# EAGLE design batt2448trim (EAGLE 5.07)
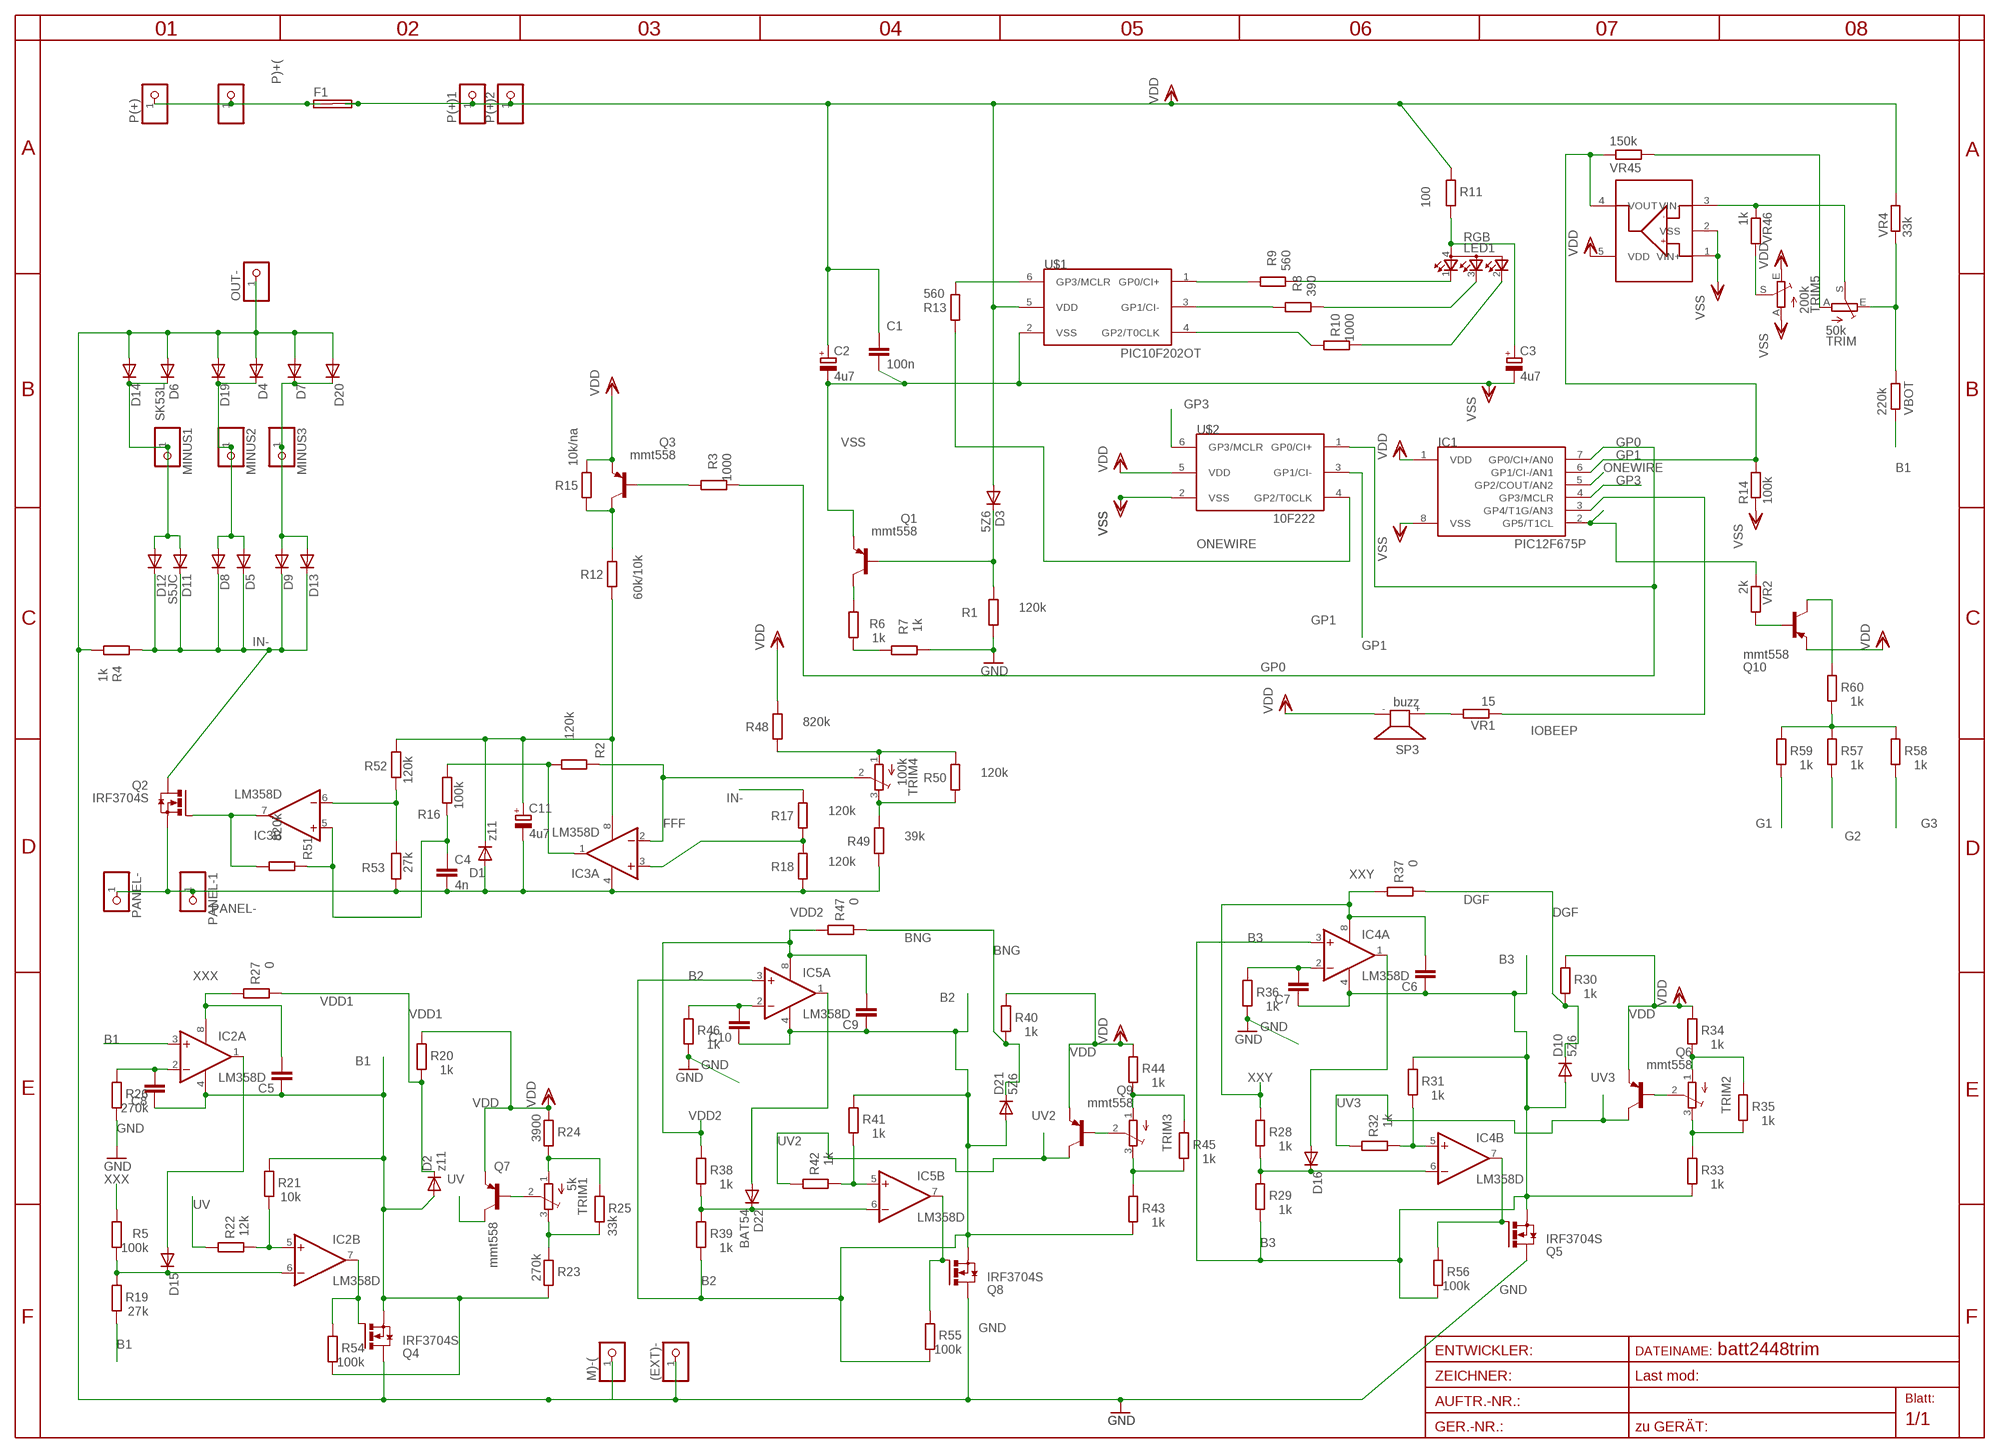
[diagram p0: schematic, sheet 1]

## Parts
(EXT)-  PINHD-1X11MM6  [1X1MM8]
C1  100n  C-EUC1206  [C1206]
C2  4u7  CPOL-EUSMCA  [SMC_A]
C3  4u7  CPOL-EUSMCA  [SMC_A]
C4  4n  C-EUC0805  [C0805]
C5  C-EUC1206  [C1206]
C6  C-EUC1206  [C1206]
C7  C-EUC0805  [C0805]
C8  C-EUC0805  [C0805]
C9  C-EUC1206  [C1206]
C10  C-EUC0805  [C0805]
C11  4u7  CPOL-EUSANYO_SMD_B6  [SANYO-OSCON_SMD_B6]
D1  z11  DIODE-MINIMELF  [MINIMELF]
D2  z11  DIODE-MINIMELF  [MINIMELF]
D3  5Z6  DIODE-MINIMELF  [MINIMELF]
D4  DIODE-SMC  [SMC]
D5  DIODE-SMC  [SMC]
D6  SK53L  DIODE-SMC  [SMC]
D7  DIODE-SMC  [SMC]
D8  DIODE-SMC  [SMC]
D9  DIODE-SMC  [SMC]
D10  5Z6  DIODE-MINIMELF  [MINIMELF]
D11  S5JC  DIODE-SMC  [SMC]
D12  DIODE-SMC  [SMC]
D13  DIODE-SMC  [SMC]
D14  DIODE-SMC  [SMC]
D15  DIODE-MINIMELF  [MINIMELF]
D16  DIODE-MINIMELF  [MINIMELF]
D19  DIODE-SMC  [SMC]
D20  DIODE-SMC  [SMC]
D21  5Z6  DIODE-MINIMELF  [MINIMELF]
D22  BAT54  DIODE-MINIMELF  [MINIMELF]
F1  SHK20L7MM5  [7MM5]
IC1  PIC12F675P  [DIL8]
IC2  LM358D  [SO08]
IC3  LM358D  [SO08]
IC4  LM358D  [SO08]
IC5  LM358D  [SO08]
IC6  MCP6001U  [SOT23-5L]
LED1  RGB  GM1WA55311A  [FULL3528]
M)-(  PINHD-1X11MM6  [1X1MM8]
MINUS1  PINHD-1X12MM3  [1X2MM3]
MINUS2  PINHD-1X12MM3  [1X2MM3]
MINUS3  PINHD-1X12MM3  [1X2MM3]
OUT-  PINHD-1X12MM3  [1X2MM3]
P(+)  PINHD-1X14.5MM  [1X4MM5]
P(+)1  PINHD-1X14.5MM  [1X4MM5]
P(+)2  PINHD-1X13MM2  [1X3MM2]
P)+(  PINHD-1X11X0.4  [1X01]
PANEL-  PINHD-1X12MM3  [1X2MM3]
PANEL-1  PINHD-1X11MM6  [1X1MM8]
Q1  mmt558  BC857ALT1SMD  [SOT23-BEC]
Q2  IRF3704S  [D2PACK]
Q3  mmt558  BC857ALT1SMD  [SOT23-BEC]
Q4  IRF3704S  [D2PACK]
Q5  IRF3704S  [D2PACK]
Q6  mmt558  BC857ALT1SMD  [SOT23-BEC]
Q7  mmt558  BC857ALT1SMD  [SOT23-BEC]
Q8  IRF3704S  [D2PACK]
Q9  mmt558  BC857ALT1SMD  [SOT23-BEC]
Q10  mmt558  BC857ALT1SMD  [SOT23-BEC]
R1  120k  R-EU_R1206  [R1206]
R2  120k  R-EU_R0805  [R0805]
R3  1000  R-EU_R0805  [R0805]
R4  1k  R-EU_0207/25  [0207/25]
R5  100k  R-EU_R1206  [R1206]
R6  1k  R-EU_R1206  [R1206]
R7  1k  R-EU_R1206  [R1206]
R8  390  R-EU_R0805  [R0805]
R9  560  R-EU_R0805  [R0805]
R10  1000  R-EU_R0805  [R0805]
R11  100  R-EU_R1206  [R1206]
R12  60k/10k  R-EU_R1206  [R1206]
R13  560  R-EU_R0805  [R0805]
R14  100k  R-EU_R1206  [R1206]
R15  10k/na  R-EU_R0805  [R0805]
R16  100k  R-EU_R0805  [R0805]
R17  120k  R-EU_R0805  [R0805]
R18  120k  R-EU_R0805  [R0805]
R19  27k  R-EU_R0805  [R0805]
R20  1k  R-EU_R1206  [R1206]
R21  10k  R-EU_R0805  [R0805]
R22  12k  R-EU_R1206  [R1206]
R23  270k  R-EU_R0805  [R0805]
R24  3900  R-EU_R0805  [R0805]
R25  33k  R-EU_R0805  [R0805]
R26  270k  R-EU_R1206  [R1206]
R27  0  R-EU_R1203  [R1203]
R28  1k  R-EU_R1206  [R1206]
R29  1k  R-EU_R0805  [R0805]
R30  1k  R-EU_R1206  [R1206]
R31  1k  R-EU_R0805  [R0805]
R32  1k  R-EU_R1206  [R1206]
R33  1k  R-EU_R0805  [R0805]
R34  1k  R-EU_R0805  [R0805]
R35  1k  R-EU_R0805  [R0805]
R36  1k  R-EU_R1206  [R1206]
R37  0  R-EU_R1203  [R1203]
R38  1k  R-EU_R1206  [R1206]
R39  1k  R-EU_R0805  [R0805]
R40  1k  R-EU_R1206  [R1206]
R41  1k  R-EU_R0805  [R0805]
R42  1k  R-EU_R1206  [R1206]
R43  1k  R-EU_R0805  [R0805]
R44  1k  R-EU_R0805  [R0805]
R45  1k  R-EU_R0805  [R0805]
R46  1k  R-EU_R1206  [R1206]
R47  0  R-EU_R1203  [R1203]
R48  820k  R-EU_R0805  [R0805]
R49  39k  R-EU_R1206  [R1206]
R50  120k  R-EU_R0805  [R0805]
R51  820k  R-EU_R0805  [R0805]
R52  120k  R-EU_R1206  [R1206]
R53  27k  R-EU_R1206  [R1206]
R54  100k  R-EU_R0805  [R0805]
R55  100k  R-EU_R0805  [R0805]
R56  100k  R-EU_R0805  [R0805]
R57  1k  R-EU_0207-17MM5  [0207/17MM5]
R58  1k  R-EU_0207-17MM5  [0207/17MM5]
R59  1k  R-EU_0207/10  [0207/10]
R60  1k  R-EU_R0805  [R0805]
SP3  buzz  KSS12017MM  [KSS1202]
TRIM  50k  TRIM_EU-S64W  [S64W]
TRIM1  5k  TRIM_EU-3223G  [3223G]
TRIM2  TRIM_EU-3223G  [3223G]
TRIM3  TRIM_EU-3223G  [3223G]
TRIM4  100k  TRIM_EU-3223G  [3223G]
TRIM5  200k  TRIM_EU-S64W  [S64W]
U$1  PIC10F202OT  [SOT23-6]
U$2  10F222  PIC10F204OT  [SOT23-6]
VBOT  220k  R-EU_R0805  [R0805]
VR1  15  R-EU_R0805  [R0805]
VR2  2k  R-EU_R0805  [R0805]
VR4  33k  R-EU_R1206  [R1206]
VR45  150k  R-EU_R0805  [R0805]
VR46  1k  R-EU_R0805  [R0805]

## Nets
A: C3.+ LED1.4(A) R11.1
B: LED1.3(CBLUE) R8.1
B1: C5.1 C8.1 D2.A D6.C D11.A D12.A D14.C IC2.3(A:+IN) IC2.4(P:V-) MINUS1.1 Q4.3(S) R19.1 R21.2 R23.1 R54.1 VBOT.1
B2: C9.1 C10.1 D7.C D9.A D13.A D20.C D21.A IC5.3(A:+IN) IC5.4(P:V-) MINUS3.1 Q8.3(S) R39.1 R41.2 R43.1 R55.1
B3: C6.1 C7.1 D4.C D5.A D8.A D10.A D19.C IC4.3(A:+IN) IC4.4(P:V-) MINUS2.1 Q5.3(S) R29.1 R31.2 R33.1 R56.1
BNG: D21.C R40.1 R47.1
BUZZ+: SP3.+ VR1.2
DGF: D10.C R30.1 R37.1
DIGOUT: R57.2 R58.2 R59.2 R60.1
FFF: IC3.2(A:-IN) R2.2 TRIM4.2(S)
G: LED1.2(CGREEN) R10.1
G1: IC2.7(B:OUT) Q4.1(G) R54.2 R59.1
G2: IC5.7(B:OUT) Q8.1(G) R55.2 R57.1
G3: IC4.7(B:OUT) Q5.1(G) R56.2 R58.1
GND: (EXT)-.1 D4.A D6.A D7.A D14.A D19.A D20.A M)-(.1 OUT-.1 Q4.2(D) Q5.2(D) Q8.2(D) R1.2 R4.1 R7.1 R26.1 R36.1 R46.1
GP0: IC1.7(GP0/CI+/AN0) R3.1 U$2.1(GP0/CI+)
GP0C: R9.2 U$1.1(GP0/CI+)
GP1: IC1.6(GP1/CI-/AN1) IC6.4(VOUT) R14.2 U$2.3(GP1/CI-) VR45.1
GP1C: R8.2 U$1.3(GP1/CI-)
GP2C: R10.2 U$1.4(GP2/T0CLK)
GP3: IC1.4(GP3/MCLR) U$2.6(GP3/MCLR)
GP3_2: R13.1 U$1.6(GP3/MCLR)
IN+: F1.1A F1.1B P(+).1 P)+(.1
IN-: D5.C D8.C D9.C D11.C D12.C D13.C Q2.2(D) R4.2 R17.1
IOBEEP: IC1.3(GP4/T1G/AN3) VR1.1
N$1: D15.C IC2.6(B:-IN) R5.1 R19.2
N$2: D3.C Q1.B R1.1
N$4: C11.+ D1.C IC3.8(P:V+) R12.2 R52.1
N$5: TRIM.E VBOT.2 VR4.1
N$6: Q1.C R6.2
N$7: TRIM5.S VR46.2
N$8: Q3.B R3.2
N$9: Q10.B VR2.2
N$10: IC2.5(B:+IN) R21.1 R22.1
N$11: Q3.C R12.1 R15.2
N$12: TRIM.A VR45.2
N$13: IC3.1(A:OUT) R2.1 R16.1
N$14: IC6.3(VIN-) TRIM.S VR46.1
N$16: IC3.3(A:+IN)
N$17: D15.A IC2.1(A:OUT)
N$18: R6.1 R7.2
N$19: R17.2 R18.1
N$20: C8.2 IC2.2(A:-IN) R26.2
N$21: Q7.B TRIM1.2(S)
N$22: R24.1 R25.2 TRIM1.1(A)
N$23: R23.2 R25.1 TRIM1.3(E)
N$24: IC3.6(B:-IN) R52.2 R53.1
N$25: D16.C IC4.6(B:-IN) R28.1 R29.2
N$26: IC4.5(B:+IN) R31.1 R32.1
N$27: Q6.B TRIM2.2(S)
N$30: R34.1 R35.2 TRIM2.1(A)
N$31: R33.2 R35.1 TRIM2.3(E)
N$32: D16.A IC4.1(A:OUT)
N$33: C7.2 IC4.2(A:-IN) R36.2
N$34: Q10.C R60.2
N$35: D22.C IC5.6(B:-IN) R38.1 R39.2
N$36: IC5.5(B:+IN) R41.1 R42.1
N$37: Q9.B TRIM3.2(S)
N$38: IC1.2(GP5/T1CL) VR2.1
N$39: R44.1 R45.2 TRIM3.1(A)
N$40: R43.2 R45.1 TRIM3.3(E)
N$41: D22.A IC5.1(A:OUT)
N$42: C10.2 IC5.2(A:-IN) R46.2
N$43: R49.1 R50.2 TRIM4.3(E)
N$45: R48.2 R50.1 TRIM4.1(A)
N$46: C4.1 IC3.5(B:+IN) R16.2 R51.2
N$47: IC3.7(B:OUT) Q2.1(G) R51.1
ONEWIRE: IC1.5(GP2/COUT/AN2) R13.2 U$2.4(GP2/T0CLK)
PANEL-: C4.2 C11.- D1.A IC3.4(P:V-) PANEL-1.1 PANEL-.1 Q2.3(S) R18.2 R49.2 R53.2
R: LED1.1(CRED) R9.1
UV: Q7.C R22.2
UV2: Q9.C R42.2
UV3: Q6.C R32.2
VDD: C1.1 C2.+ D3.A F1.2A F1.2B IC1.1(VDD) IC6.5(VDD) P(+)1.1 P(+)2.1 Q3.E Q6.E Q7.E Q9.E Q10.E R11.2 R15.1 R20.2 R24.2 R30.2 R34.2 R40.2 R44.2 R48.1 SP3.- TRIM5.E U$1.5(VDD) U$2.5(VDD) VR4.2
VDD1: D2.C R20.1 R27.1
VDD2: C9.2 IC5.8(P:V+) R38.2 R47.2
VSS: C1.2 C2.- C3.- IC1.8(VSS) IC6.1(VIN+) IC6.2(VSS) Q1.E R14.1 TRIM5.A U$1.2(VSS) U$2.2(VSS)
XXX: C5.2 IC2.8(P:V+) R5.2 R27.2
XXY: C6.2 IC4.8(P:V+) R28.2 R37.2

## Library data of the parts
(EXT)- M)-( MINUS1-MINUS3 OUT- P(+) P(+)1 P(+)2 P)+( PANEL- PANEL-1 = pinhead:PINHD-1X1: PIN HEADER
C1 C4-C10 = rcl:C-EU: CAPACITOR, European symbol
C2 C3 C11 = rcl:CPOL-EU: POLARIZED CAPACITOR, European symbol
D1-D16 D19-D22 = diode:DIODE-: DIODE
F1 = fuse:SHK20L: FUSE HOLDER 5 x 20 mm, SH contact, SHH1 Schukat, E1073 Buerklin
IC1 = microchip-3:PIC12F6*: uPC nW 1k Program Flash memory 2x Timer Comparator 10b A/D converter/ 4xIN
IC2-IC5 = linear:LM358: OP AMP also LM158; LM258; LM2904 Source: http://cache.national.com/ds/LM/LM158.pdf
IC6 = microchip-3:MCP6001U
LED1 = led:GM1WA55311A: Chip LED RGB Source: http://document.sharpsma.com/files/GM1WA55311A_SS.pdf
Q1 Q3 Q6 Q7 Q9 Q10 = transistor-pnp:BC857*: PNP Transistror
Q2 Q4 Q5 Q8 = transistor-power:IRF3704: SMPS MOSFET HEXFET® Power MOSFET Source: http://www.irf.com/product-info/datasheets/data/irf3704.pdf
R1-R13 R15-R21 R23-R26 R28-R36 R38-R46 R48-R60 VBOT VR1 VR2 VR4 VR45 VR46 = rcl-2:R-EU_: RESISTOR, European symbol
R14 R22 R27 R37 R47 = rcl:R-EU_: RESISTOR, European symbol
SP3 = buzzer:KSS1201: SPEAKER
TRIM TRIM1-TRIM5 = pot:TRIM_EU-: POTENTIOMETER
U$1 U$2 = microchip-3:PIC10F2*: uPC nW 0,25/0,5k Program Flash memory Comparator

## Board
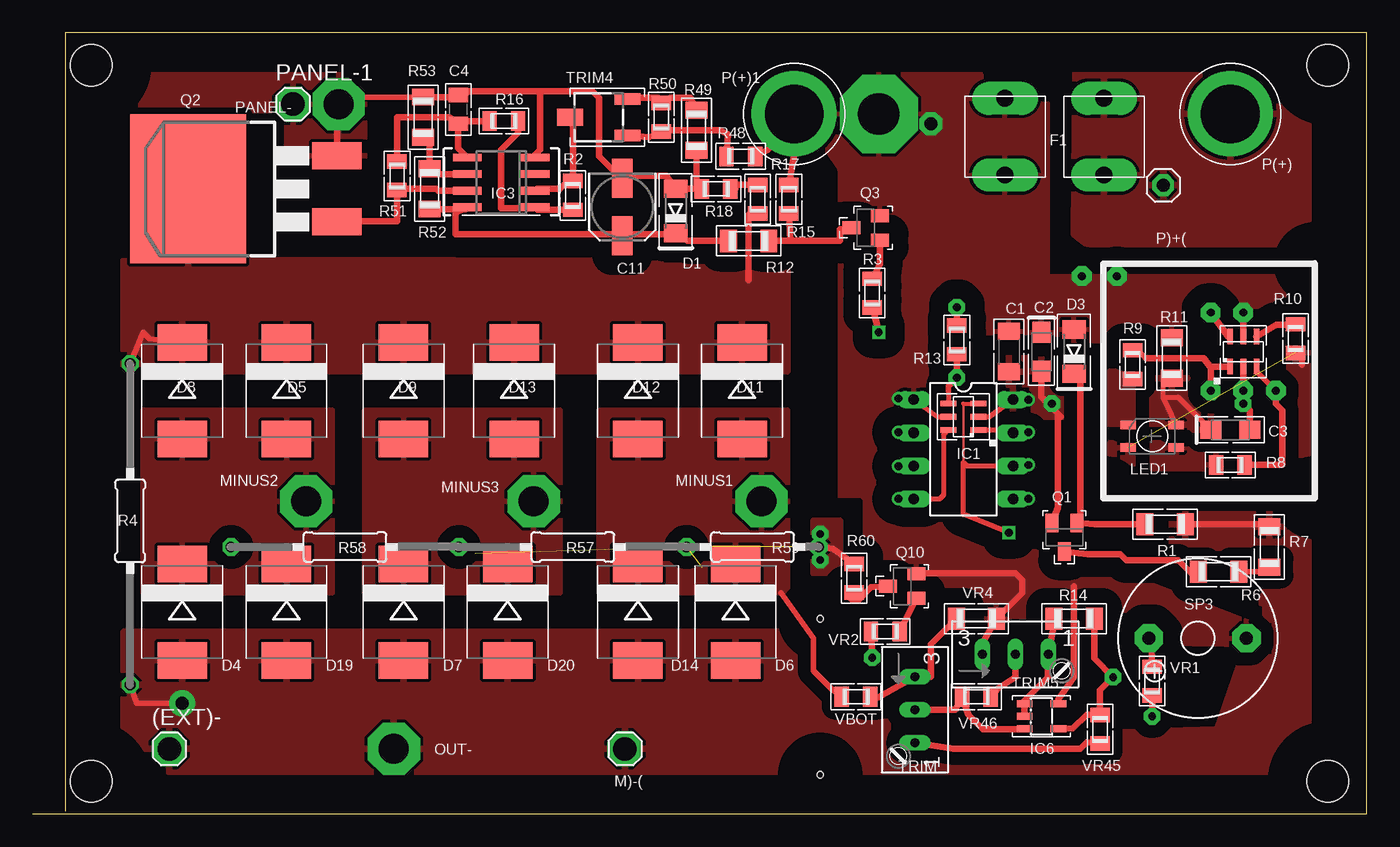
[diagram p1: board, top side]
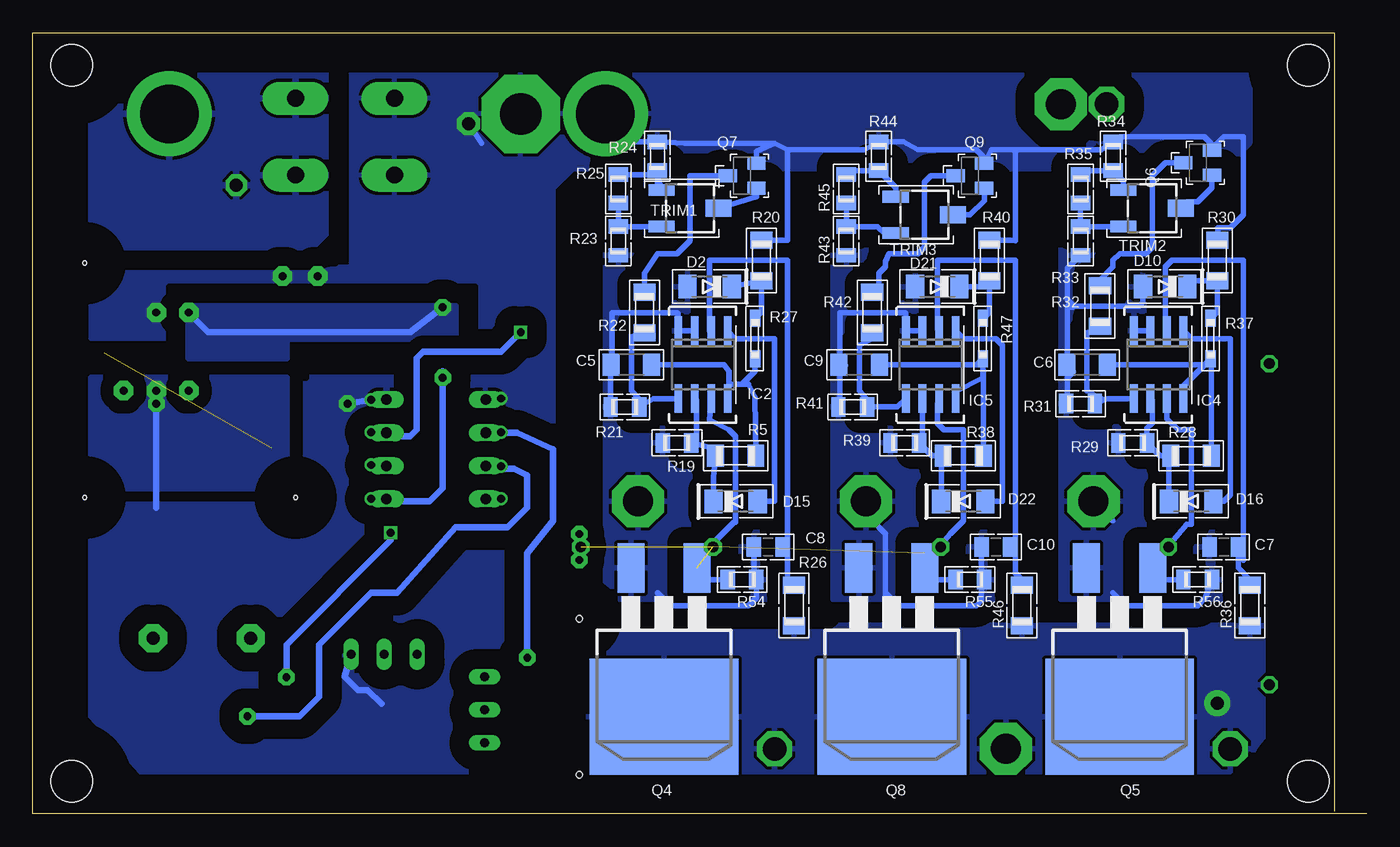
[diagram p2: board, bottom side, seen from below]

Size 102.5 x 60 mm. Coordinates in mm from the lower left corner, seen from the top.
Outline: 0,0 102.5,0 102.5,60 2.5,60 2.5,0.2
Copper layers (1*16): Top 0.035mm / dielectric 1.5mm / Bottom 0.035mm
Design rules "default *": minimum track width 8mil, minimum drill 0.3mm, track to track 8mil, track to pad 8mil, pad to pad 8mil, via to via 8mil, smd to smd 8mil, copper to edge 3mm, drill to drill 2mil, minimum pad ring 10mil, minimum via ring 8mil, stop-mask expansion 4mil, vias tented up to drill 0mil, thermal gap 10mil
Holes 3.2 mm at 4.5,57.5 4.5,2.5 99.5,57.5 99.5,2.5
Holes 0.5 mm at 60.5,15 60.5,3
Holes 0.3 mm at 98.5,24.3 82.3,24.3 98.5,42.3

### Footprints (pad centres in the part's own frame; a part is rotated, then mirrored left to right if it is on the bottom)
1X1MM8 = drill 1.8 pad 2.54 octagon: 1 0,0
C1206 = smd 1.3 x 1.7: 1 -1.55,0; 2 1.55,0
SMC_A = smd 1.6 x 1.4: + -1.5,0; - 1.5,0
C0805 = smd 1.1 x 1.5: 1 -1.1,0; 2 1.1,0
SANYO-OSCON_SMD_B6 = smd 3 x 1.6: + 2.2,0; - -2.2,0
MINIMELF = smd 1.4 x 1.8: A 1.7,0; C -1.7,0
SMC = smd 2.8 x 3.8: A 3.7,0; C -3.7,0
7MM5 = drill 1.3 pad 2.54 long: 1A -3.8,2.94; 1B -3.8,-2.94; 2A 3.8,2.94; 2B 3.8,-2.94
DIL8 = drill 0.813 long: 1 -3.81,-3.81; 2 -1.27,-3.81; 3 1.27,-3.81; 4 3.81,-3.81; 5 3.81,3.81; 6 1.27,3.81; 7 -1.27,3.81; 8 -3.81,3.81
SO08 = smd 0.6 x 2.2: 1 -1.905,-2.6; 2 -0.635,-2.6; 3 0.635,-2.6; 4 1.905,-2.6; 5 1.905,2.6; 6 0.635,2.6; 7 -0.635,2.6; 8 -1.905,2.6
SOT23-5L = smd 0.55 x 1.2: 1 -0.95,-1.3; 2 0,-1.3; 3 0.95,-1.3; 4 0.95,1.3; 5 -0.95,1.3
FULL3528 = smd 0.65 x 1.2: 1 0.875,1.85; 2 -0.875,1.85; 3 -0.875,-1.85; 4 0.875,-1.85
1X2MM3 = drill 2.3 pad 4 octagon: 1 0,0
1X4MM5 = drill 4.5 pad 6.35 round: 1 0,0
1X3MM2 = drill 3.2 pad 6 octagon: 1 0,0
1X01 = drill 1 pad 1.676 octagon: 1 0,0
SOT23-BEC = smd 1 x 1.4: B -0.95,-1.1; C 0,1.1; E 0.95,-1.1
D2PACK = smd 2.083 x 3.81: 1 -2.54,-8.89; 3 2.54,-8.89 | smd 11.43 x 8.89: 2 0,2.54
R1206 = smd 1.3 x 1.7: 1 -1.55,0; 2 1.55,0
R0805 = smd 1.1 x 1.5: 1 -1.1,0; 2 1.1,0
0207/25 = drill 0.813 octagon: 1 -12.58,0; 2 12.08,0
R1203 = smd 1.3 x 0.8: 1 -1.55,0; 2 1.55,0
0207/17MM5 = drill 0.813 octagon: 1 -8.75,0; 2 8.75,0
0207/10 = drill 0.813 octagon: 1 -5.08,0; 2 5.08,0
KSS1202 = drill 1 pad 2.159 octagon: + 3.75,0; - -3.75,0
S64W = drill 0.7 long: A 2.54,1.27; E -2.54,1.27; S 0,1.27
3223G = smd 2 x 0.9: 1 -2.2,1.4; 3 -2.2,-1.4 | smd 2 x 1.3: 2 2.2,0
SOT23-6 = smd 0.45 x 1.2: 1 -1.016,-1.15; 2 0,-1.15; 3 1.016,-1.15; 4 1.016,1.15; 5 0,1.15; 6 -1.016,1.15

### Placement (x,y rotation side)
(EXT)-  10.5,5 0 top
C1  75,35.5 270 top
C2  77.5,35.5 270 top
C3  92,29.5 0 top
C4  32.7,54.1 90 top
C5  56.5,34.5 0 bottom
C6  21.5,34.5 0 bottom
C7  11,20.5 0 bottom
C8  46,20.5 0 bottom
C9  39,34.5 0 bottom
C10  28.5,20.5 0 bottom
C11  45.3,46.6 270 top
D1  49.4,46.3 90 top
D2  50.5,40.5 180 bottom
D3  80,35.5 90 top
D4  11.5,15.5 270 top
D5  19.5,32.5 270 top
D6  54,15.5 270 top
D7  28.5,15.5 270 top
D8  11.5,32.5 270 top
D9  28.5,32.5 270 top
D10  15.5,40.5 180 bottom
D11  54.5,32.5 270 top
D12  46.5,32.5 270 top
D13  37,32.5 270 top
D14  46.5,15.5 270 top
D15  48.5,24 0 bottom
D16  13.5,24 0 bottom
D19  19.5,15.5 270 top
D20  36.5,15.5 270 top
D21  33,40.5 180 bottom
D22  31,24 0 bottom
F1  78.5,52 180 top
IC1  71.5,28 270 top
IC2  51,34.5 180 bottom
IC3  36,48.5 90 top
IC4  16,34.5 180 bottom
IC5  33.5,34.5 180 bottom
IC6  77.5,7.5 270 top
LED1  86,29 90 top
M)-(  45.5,5 0 top
MINUS1  56,24 180 top
MINUS2  21,24 180 top
MINUS3  38.5,24 180 top
OUT-  27.75,5 180 top
P(+)  92,53.75 0 top
P(+)1  58.5,53.75 0 top
P(+)2  65,53.75 0 top
P)+(  86.84,48.27 0 top
PANEL-  23.5,54.5 180 top
PANEL-1  20,54.5 0 top
Q1  79.25,21.25 180 top
Q2  14.5,48 90 top
Q3  64,45 90 top
Q4  54,10 180 bottom
Q5  19,10 180 bottom
Q6  13,50 90 bottom
Q7  48,49 90 bottom
Q8  36.5,10 180 bottom
Q9  30.5,49 90 bottom
Q10  66.8,17.5 90 top
R1  87,22.25 0 top
R2  41.5,47.5 90 top
R3  64.5,40 90 top
R4  7.5,22.5 90 top
R5  48.5,27.5 0 bottom
R6  91.1,18.6 180 top
R7  95,20.5 270 top
R8  92,26.8 0 top
R9  84.5,34.5 90 top
R10  97,36.5 90 top
R11  87.5,35 90 top
R12  55,44 180 top
R13  71,36.4 270 top
R14  80,15 0 top
R15  58.1,47.2 270 top
R16  36.2,53.2 180 top
R17  55.7,47.2 90 top
R18  52.5,48 180 top
R19  53,28.5 0 bottom
R20  46.5,42.5 90 bottom
R21  57,31.25 180 bottom
R22  55.5,38.5 90 bottom
R23  57.5,44 90 bottom
R24  54.5,50.5 90 bottom
R25  57.5,48 90 bottom
R26  44,16 90 bottom
R27  47,36.5 270 bottom
R28  13.5,27.5 0 bottom
R29  18,28.5 0 bottom
R30  11.5,42.5 90 bottom
R31  22,31.5 180 bottom
R32  20.5,39 90 bottom
R33  22,44 90 bottom
R34  19.5,50.5 90 bottom
R35  22,48 90 bottom
R36  9,16 90 bottom
R37  12,36.5 270 bottom
R38  31,27.5 0 bottom
R39  35.5,28.5 0 bottom
R40  29,42.5 90 bottom
R41  39.5,31.25 180 bottom
R42  38,38.5 90 bottom
R43  40,44 90 bottom
R44  37.5,50.5 90 bottom
R45  40,48 90 bottom
R46  26.5,16 90 bottom
R47  29.5,36.5 270 bottom
R48  54.4,50.5 180 top
R49  51,52.5 270 top
R50  48.3,53.5 90 top
R51  28,49 90 top
R52  30.5,48 90 top
R53  30,53.5 90 top
R54  48,18 180 bottom
R55  30.5,18 180 bottom
R56  13,18 180 bottom
R57  41.5,20.5 0 top
R58  24,20.5 0 top
R59  55.3,20.5 0 top
R60  63.1,18.1 270 top
SP3  89.5,13.5 180 top
TRIM  66.5,8 270 top
TRIM1  52,46.5 0 bottom
TRIM2  16.5,46.5 0 bottom
TRIM3  34,46 0 bottom
TRIM4  43.5,53.5 180 top
TRIM5  75.5,11 0 top
U$1  93,35.5 0 top
U$2  71.5,30.5 90 top
VBOT  63.25,9 0 top
VR1  86,10.2 90 top
VR2  65.5,14 0 top
VR4  72.5,15 0 top
VR45  82,6.5 270 top
VR46  72.5,9 0 top

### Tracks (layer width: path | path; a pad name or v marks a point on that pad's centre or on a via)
A
  Top 0.4: 86.85,32 86.85,33.3 R11.1 | LED1.4 86.85,32 | C3.+ 88,32 86.85,32
  pour Top (isolate 1, rank 2): 86,34 91,34 91,29.5 86,29.5
B
  pour Top (isolate 1.016): 86,28.5 87.5,28.5 88,28 92,28 92,26.5 86,26.5
B1
  Top 0.406: VBOT.1 61.5,9.5 60,11 60,13.5 57.5,17
  Bottom 0.406: IC2.3 IC2.4 52.91,38.41 53,38.5 58,38.5 58,34.95 C5.1 58.1,34.5 R21.2 | 54.5,17 53.5,16 47.5,16 46.9,16.6 R54.1 47.1,18.8 C8.1
  pour Top (isolate 1, rank 2): 58,17 43.5,17 43.5,31 58,31
  pour Bottom (isolate 1.25, rank 4): 58.5,16.5 44,16.5 44,43.5 58.5,43.5
B2
  Bottom 0.406: IC5.3 IC5.4 35.41,38.41 35.5,38.5 40.5,38.5 40.5,34.95 C9.1 40.05,34.45 40.5,34 40.5,31.65 R41.2 | 37,17 37,16.5 | 37,17 37,21.5 37.5,22 MINUS3.1 | 29.6,18.3 C10.1 | 29.6,18.3 R55.1 | 29.6,18.3 29.6,16.4 30,16 36,16 37,17
  pour Top (isolate 1, rank 3): 25.5,17 25.5,31 40.5,31 40.5,17
  pour Bottom (isolate 1.25, rank 3): 25.5,16.5 25.5,43.5 41,43.5 41,16.5
B3
  Bottom 0.406: D10.A 17.2,39.3 17.5,39 22.5,39 | 22.5,39 23,39.5 23,41.9 R33.1 | 19.5,22.5 MINUS2.1 | IC4.3 IC4.4 | 22.5,39 22.6,38.9 22.9,38.9 23,39 23,34.95 C6.1 22.55,33.95 23,33.5 23,31.9 R31.2 | R56.1 12.4,16.6 13,16 18.5,16 19.5,17
  pour Top (isolate 1, rank 4): 8.5,17 8.5,31 23,31 23,17
  pour Bottom (isolate 1.25, rank 4): 8,16.5 8,43.5 23.5,43.5 23.5,16.5
BNG
  Bottom 0.406: R47.1 29.45,38.05 29,38.5 R40.1 29.45,40.5 D21.C
BUZZ+
  Top 0.5: VR1.2 85.89,13.36 SP3.+
DGF
  Bottom 0.406: R37.1 11.5,38.55 R30.1 13.35,40.95 D10.C
DIGOUT  (via drill 0.6 pad 1.27)  (2 unrouted)
  Top 0.5: R60.1 61.5,20.35 R59.2
  Bottom 0.406: R58.2 33.5,20.5 34,20
  other vias: 60.5,19.5 60.5,21.5
  pour Top (isolate 1.5): 60,22.5 62,22.5 62,18 60.5,18 60,18.5
FFF
  Top 0.5: TRIM4.2 41.5,52.8 R2.2 41.1,48.6 40.5,48 38.73,48 IC3.2
G  (1 unrouted)
  Top 0.5: R10.1 97.5,35.4 97.5,34.5
  pour Top (isolate 1, rank 2): 82.75,28.5 84.5,28.5 84.5,26.5 96.5,26.5 96.5,36 98,36 98,24.75 82.75,24.75
G1  (1 unrouted)
  Bottom 0.406: IC2.7 50.5,30.27 49,29.5 48.5,29 48.5,22.39 48.61,22.39 50,21 50,20.85 R59.1 | R54.2 50.96,18 Q4.1
G2
  Bottom 0.406: IC5.7 32.86,31.64 33,31.5 33,30 32.5,29.5 31,29.5 31,22.5 32,21.5 32.47,20.98 | 32.47,20.98 33.35,20 Q8.1 33.07,18 R55.2 | R57.1 32.25,20.75 32.47,20.98
G3
  Bottom 0.406: IC4.7 15.37,30.36 14.5,29.5 13.5,29.5 13.5,22.25 13.82,22.25 14.7,21.25 R58.1 16,20.5 16.5,20 16.5,18.93 Q5.1 15.57,18 R56.2
GND  (via drill 1 pad 2)
  Top 0.406: v11.5,8.5 8,8.5 R4.1 | 95,22.25 R7.1
  Top 0.5: R1.2 95,22.25
  pour Top (isolate 1, rank 5): 98,2 12.3,2 7,5.5 7,14 74,14 74,6 91,6.5 95.5,19.5 87.5,19.5 87.5,23 98,23
  pour Bottom (isolate 1.422, rank 4): 59.8,2.5 12.3,2 8,5 8,14.5 40.5,14.5 41,14 59.8,14
GP0  (via drill 0.6, 0.6 pad 1)
  Top 0.4: U$2.1 75.1,29.48 IC1.7
  Top 0.406: v76.5,29.3 75.34,29.3 IC1.7
  Top 0.5: v65,37 R3.1
  Bottom 0.5: v76.5,29.3 76.7,29.5 | v65,37 66.5,35.5 72.5,35.5 73,35 73,29.5 73.5,29 75.04,29 IC1.7
GP0C  (via drill 0.6 pad 1.5)
  Top 0.4: R9.2 84.9,35.6 85.5,35
  Top 0.5: 90.5,34.25 v90.5,32.5 | 85.5,35 89.97,35 90.5,34.25 | U$1.1 90.6,34.35 90.5,34.25
GP1  (via drill 0.6, 0.6 pad 1, 0.6 pad 1.27)
  Top 0.2: 71.5,27 71.5,31.5
  Top 0.3: 71.5,31.5 72.63,31.5
  Top 0.4: IC1.6 71.77,26.73 71.5,27 71.5,23 v75,21.6
  Top 0.406: IC1.6 76.43,26.73 v76.5,26.8 | 72.63,31.5 U$2.3
  Top 0.5: IC6.4 79.05,6.55 79.9,6.6 81,7.6 VR45.1 82,9.5 v83,10.5 81.55,11.95 R14.2 81.5,14.95
  Bottom 0.5: v83,10.5 83,13 75,21 v75,21.6
GP1C  (via drill 0.6 pad 1.5)
  Top 0.4: U$1.3 94.02,33.98 v95.5,32.5
  Top 0.5: v95.5,32.5 95.5,31.5 96,31 96,26.8 R8.2
GP2C
  Top 0.5: U$1.4 95.55,37.55 97,37.55 R10.2
GP3  (via drill 0.6 pad 1)
  Top 0.4: IC1.4 69.69,24.19 70,24.5 70,29.13 U$2.6
  Top 0.406: IC1.4 v66.51,24.19 v66.5,24.2
GP3_2  (via drill 0.6 pad 1.27, 0.6 pad 1.5)
  Top 0.5: U$1.6 91.85,36.65 v90.5,38.5 | R13.1 v71,38.9
  Bottom 0.5: v90.5,38.5 89,37 73.5,37 v71,38.9
  pour Bottom (isolate 1): 70,39 90.5,39 90.5,35 83,35 83,36.5 70,36.5
IN+
  pour Top (isolate 1.5): 80.1,57 98,57 98,43.75 81,43.75 80,44.5
  pour Bottom (isolate 1.5): 80,57 98,57 98,43.5 81,43.5 80,44.5
IN-
  Top 0.406: R4.2 8.5,37 9,36.5 D8.C
  Top 0.5: R17.1 55,46 55,41
  pour Top (isolate 1.5): 7,42.5 58,42.5 58,34 7,34
IOBEEP  (via drill 0.6 pad 1, 0.6 pad 1.27)
  Top 0.5: VR1.1 86.01,8.11 v86,7.5
  Bottom 0.406: 67.46,26.5 IC1.3
  Bottom 0.5: 67.46,26.5 66.5,26.5 v66.5,26.7 66.3,26.5 65.5,26.5 64.5,26 64.5,23.5 66,22 70,22 74.5,17 76.5,17 80.5,13 80.5,9 82,7.5 v86,7.5
N$1
  Bottom 0.406: D15.C 50.2,25.85 R5.1 50.55,28.15 R19.2 51.5,28.5 51.5,31.77 IC2.6
N$2
  Top 0.5: D3.C 80.22,33.78 80.5,33.5 80.5,22.65 Q1.B 81.6,22.25 R1.1
N$3  (via drill 0.6 pad 1)
  other vias: 76.5,24.2
N$4
  Top 0.5: R52.1 33.25,46.45 IC3.8 32.5,46.2 32.5,44.5 45.4,44.5 | R12.2 50.3,44 D1.C 49,45 48.5,44.5 45.5,44.5 | 45.4,44.5 45.5,44.5 | 45.4,44.5 C11.+ 45.4,44.4 45.5,44.5
N$5
  Top 0.5: VBOT.2 64.96,8.95 TRIM.E 69,10.54 69,13.05 VR4.1
N$6
  Top 0.5: R6.2 89,18.5 88,19.5 84,19.5 83.55,19.95 81.05,19.95 Q1.C
N$7
  Top 0.5: VR46.2 74.1,9.6 75.5,10.5 TRIM5.S
N$8
  Top 0.5: Q3.B 65.1,42.2 R3.2
N$9
  Top 0.5: VR2.2 Q10.B
N$10
  Bottom 0.406: IC2.5 54.8,31.9 R21.1 55.9,31.9 56.5,32.5 56.5,36.65 R22.1
N$11
  Top 0.5: 58.2,44 R15.2 | R12.1 58.2,44 | 58.2,44 62,44 62,44.9 Q3.C
N$12
  Top 0.5: VR45.2 81,5.5 80.5,5 70.73,5 TRIM.A
N$13
  Top 0.5: R16.1 37.3,52.3 36,51 36,46.5 38.01,46.5 IC3.1 38.8,46.4 R2.1
N$14
  Top 0.5: TRIM.S 70.9,8 VR46.1 71.9,7.6 73,6.5 75.65,6.5 IC6.3
N$17
  Bottom 0.406: D15.A 45.5,24 45.5,36.5 48.59,36.5 IC2.1
N$18
  Top 0.406: R6.1 94.85,18.6 R7.2
N$19
  Top 0.5: R18.1 54,48 54,48.3 R17.2
N$20
  Bottom 0.406: R26.2 44.5,17.55 | 44.5,17.55 44.5,20.5 | 44.5,20.5 44.5,42.5 50.5,42.5 50.5,37.1 IC2.2 | 44.5,17.55 44.55,17.6 | 44.5,20.5 C8.2
N$21
  Bottom 0.406: Q7.B 46.9,47.4 TRIM1.2
N$22
  Bottom 0.406: 54.5,49.1 R25.2 | 54.5,49.1 TRIM1.1 54.5,48.2 54.5,49.1 | 54.5,49.1 R24.1
N$23
  Bottom 0.406: R25.1 R23.2 TRIM1.3
N$24
  Top 0.5: R53.1 30.5,51.45 R52.2 30.91,49.13 IC3.6
N$25
  Bottom 0.406: D16.C 15.2,27.35 R28.1 15.9,27.5 R29.2 16.9,29.6 16.5,30 16.5,31.77 IC4.6
N$26
  Bottom 0.406: IC4.5 20,31.9 R31.1 20.4,31.9 21.5,32.5 21.5,36.95 R32.1
N$27
  Bottom 0.406: Q6.B 11.9,48.1 13,47 13.8,47 TRIM2.2
N$29  (via drill 0.6 pad 1)
  other vias: 66.5,29.3
N$30
  Bottom 0.406: R35.2 21.7,49.4 R34.1 18.7,48.6 TRIM2.1
N$31
  Bottom 0.406: R35.1 R33.2 TRIM2.3
N$32
  Bottom 0.406: IC4.1 13.5,36.5 10.5,36.5 10.5,24.5 11,24 D16.A
N$33
  Bottom 0.406: 9.5,20 9.5,19.5 | 9.5,20 9.5,42.5 15,42.5 15.5,42 15.5,37.23 IC4.2 | 9.9,19.6 C7.2 | R36.2 9,18 9.9,18.9 9.9,19.6 | 9.9,19.6 9.5,20
N$34
  Top 0.5: Q10.C 64.4,17.4 63.5,16.5 62.9,16.5 R60.2
N$35
  Bottom 0.406: D22.C 32.7,27.35 R38.1 33.4,27.5 R39.2 34.14,28.77 IC5.6
N$36
  Bottom 0.406: R42.1 38,36.5 39,36 39,32.5 38,31.35 R41.1 36.05,31.25 IC5.5
N$37
  Bottom 0.406: Q9.B 29.4,47.1 30.5,46 TRIM3.2
N$38  (via drill 0.6 pad 1.27)
  Top 0.5: v64.5,12 VR2.1
  Bottom 0.5: IC1.2 65.27,29.27 62.5,28 62.5,22.5 64.5,20 v64.5,12
N$39
  Bottom 0.406: TRIM3.1 36.2,48.1 R44.1 39.7,49.4 R45.2
N$40
  Bottom 0.406: R45.1 R43.2 37.6,45.1 37,44.5 36.3,44.5 TRIM3.3
N$41
  Bottom 0.406: D22.A 28,24 28,36 28.5,36.5 31,36.5 IC5.1
N$42
  Bottom 0.406: 27,20.5 27,18.5 26.5,18 R46.2 | 27,20.5 27,42.5 33,42.5 33,37.23 IC5.2 | 27,20.5 C10.2
N$43
  Top 0.5: TRIM4.3 45.9,54.9 46.5,55 48.05,55 R50.2 48.55,54.55 49,55 50.55,55 R49.1
N$45
  Top 0.5: R48.2 53.4,52.2 52.8,52.5 49.05,52.5 R50.1 47.35,51.95 TRIM4.1
N$46
  Top 0.5: R51.2 28,53.5 32,53.5 C4.1 | C4.1 32.7,51.1 IC3.5 | R16.2 33.1,53.2 C4.1
N$47
  Top 0.5: IC3.7 31.14,47.87 31,48 28.1,48 R51.1 28,45.5 23.5,45.5 23.46,45.46 Q2.1
ONEWIRE  (via drill 0.6 pad 1.27)
  Top 0.4: 70.35,32.5 U$2.4
  Top 0.406: v71,33.5 70.35,32.85 70.35,32.5
  Top 0.5: v71,33.5 R13.2
  Bottom 0.406: 71,34 v71,33.5 | 75.12,24 IC1.5
  Bottom 0.5: 75.12,24 72,24 71,25 71,34
PANEL-
  Top 0.406: R53.2 24.44,55.05 23.39,54
  Top 0.5: 39,55.5 43,55.5 43.5,55 43.5,50.5 44.5,49.5 44.6,49.5 C11.- 45.2,48.8 45,49 48.7,49 D1.A | 39,55.5 33.5,55.5 33.2,55.2 C4.2 32.65,55.05 R53.2 | IC3.4 38.6,50.6 39,51 39,55.5 | D1.A 48.8,48.5 | D1.A R18.2 51,48.1 R49.2 | Q2.3 23.39,54 23.39,54.89 PANEL-.1
  pour Top (isolate 0.5): 7.5,57.5 25.5,57.5 25.5,50 19.5,50 19.5,54 7.5,54
R
  pour Top (isolate 1, rank 3, no thermals): 82.75,34 84.5,34 84.5,29.5 82.75,29.5
UV
  Bottom 0.406: Q7.C 52,49 52,44 53,43 54.5,43 55.5,41.5 R22.2 55.5,40.25
UV2
  Bottom 0.406: Q9.C 33.5,49 34,48.5 34,43.5 34.5,43 36.7,43 37,42.4 37,42 37.5,41.5 37.5,40.55 R42.2
UV3
  Bottom 0.406: Q6.C 15.5,50 16.5,49 16.5,43.5 17,43 19,43 19.5,42.5 19.5,42 20.5,41 R32.2 20.5,40.25
VDD  (via drill 0.6 pad 1, 0.6 pad 1.5, 1 pad 1.78)
  Top 0.4: U$2.5 69.5,30.5 IC1.1 67.5,32
  Top 0.406: SP3.- 93.25,14.25
  Top 0.5: U$1.5 v93,38.5 | R48.1 56.5,51 58.5,53 P(+)1.1 59,53.5 R15.1 | TRIM5.E 73.06,13.29 VR4.2 76.05,17 76.05,17.95 75.5,18.5 68,18.5 | IC6.5 78.8,8.8 80,10.5 80,17.5 | 67.5,32 66.6,32 v66.5,31.9
  Bottom 0.406: R20.2 44.5,44.05 44.5,51 | 44.5,51 45.5,51.5 | 45.5,51.5 52.4,51.5 R24.2 57.4,51.6 | Q7.E 46.9,50.9 45.5,51.5 | 68,51.5 v69,53 | R30.2 11.45,45 10.5,45 9.5,46 9.5,52 11,52 11.9,51.1 Q6.E 12,51.05 12,51.5 12.5,52 19,52 19.4,51.6 R34.2 20.4,51 27,51 | R40.2 27.05,44.05 27,44 27,51 | 27,51 28.85,51 Q9.E 29.5,50.05 29.5,50.5 30,51 34.5,51 35.6,51.6 R44.2 38.6,51 44.5,51
  other vias: 80.6,41.3 83.3,41.3
  pour Top (isolate 1.5, rank 3): 78,41.25 78,54.5 74,54.5 72.5,57.5 59.5,57.5 61,51 62,49.5 62,13.5 94,13 94,14.5 68,24.5 68.5,32 69,32.5 73,37 74,36.5 98,36 98,41.25
  pour Bottom (isolate 1.5, rank 2): 78,42 78,57.5 62,57 9,57 9,51.5 11,49.5 61,49.5 62.5,48 62.5,30 68.5,30 68.5,32 69,32.5 73,37 74,36.5 98,36.5 98,42
VDD1
  Bottom 0.406: D2.C R20.1 46.5,38.55 R27.1
VDD2
  Bottom 0.406: R38.2 29.45,33.4 R47.2 | IC5.8 31.59,32.41 29.5,33.5 R47.2 | C9.2 29.95,34.5 R47.2
VSS  (via drill 0.6 pad 1, 0.6 pad 1.27, 0.6 pad 1.5)
  Top 0.4: U$2.2 73.5,30.5
  Top 0.406: 73.5,30.5 IC1.8
  Top 0.5: v93,32.5 U$1.2 | Q1.E 78.75,23.5 78.75,30.5 79,30.5 77.5,32 | 77.5,32 C2.- | 77.5,32 v78.3,31.5 | IC6.2 IC6.1 75.95,8.45 78,10.5 78,11.73 TRIM5.A 78.54,14.91 R14.1 | C3.- 93.5,31 v93,31.5
  Bottom 0.5: 93,23.5 v93,32.5 | TRIM5.A 78.54,10.54 77.5,9.5 76.75,9.5 75.7,8.45 | v78.3,31.5 v76.5,31.8
  pour Bottom (isolate 1.5, rank 5): 74.5,33.5 81.5,33.5 81.5,23.75 98,23.75 98,7.5 93.5,2.5 63.5,2.5 62,7 62,21 75,21 77.5,23.5 77.5,29 75,29 74.5,29.5
  pour Top (isolate 1): 74.5,35 79.5,35 79.5,30.5 74.5,30.5
  pour Bottom (isolate 1, rank 5): 83,33.5 98,33.5 98,25 83,25
XXX
  Bottom 0.406: C5.2 49.4,34.5 49,34 49,33 | 49,33 49,32 IC2.8 | R5.2 47,32 47.5,33 48,33 | 48,33 49,33 | R27.2 47,34 48,33
XXY
  Bottom 0.406: C6.2 12.45,34.5 R37.2 | R28.2 11.95,34.9 R37.2 | IC4.8 14.1,32.85 R37.2

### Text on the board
tTest: 4v4
Document: 1m | 10u | 10u | 300u | 2mA | 500u | 1m | 2m | 300u | 300u | 30u | 5m | 14m | 12m | 500u | 5m | 5m | 5m | 5m | 5m | 5m | 40m | 40m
